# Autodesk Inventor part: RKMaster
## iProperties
Company: Scholle und Partner GmbH
Shininess: 64.0
Length Units: 11269
Angle Units: 11279
Time Units: 11290
Mass Units: 11283
Length Display Precision: 3
Angle Display Precision: 2
Compacted: True
Part Number: RKMaster
Document SubType Name: Modeling
Created: 2004-10
Material: Standard
Designer: mp
Density: 0.0
Volumn: 0.0
Area: 0.0
PropertySet Name: Model Information
Control State: 0
Master: False
Checked Out: False
Wandstärke: 1,500 mm
SegmentAnzahl: 5,000 oE oE
Winkel: 80,00 grd grd
Author: Michael Puschner
Comments: www.scholle.de
